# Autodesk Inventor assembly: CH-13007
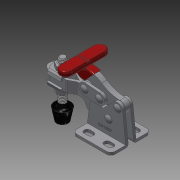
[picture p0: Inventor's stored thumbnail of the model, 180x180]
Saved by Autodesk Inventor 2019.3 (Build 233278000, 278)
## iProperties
Company: Î¢ÈíÖÐ¹ú
Created: 2012-09
Part Number: CH-13007
Material: Ogólny
Description: STEP AP203
Document SubType Name: Assembly
Designer: CADENGINEERING4
Stock Number: DOCISK PIONOWY
Sending System: SolidWorks 2010
Preprocessor: SwSTEP 2.0
Title: CH-13007.STEP
Author: Î¢ÈíÓÃ»§
Revision Number: ÈÎºÎ
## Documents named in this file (9)
- D:\Vault_2016\Projekty\Clamptek\STRONA\Vertical toggle clamp\CH-13007\CH-13007_ZAMNIETY.iam
- D:\Vault_2016\Projekty\Clamptek\STRONA\Vertical toggle clamp\CH-13007\CH-FC-56212 Nut.ipt
- D:\Vault_2016\Projekty\Clamptek\STRONA\Vertical toggle clamp\CH-13007\CH-13007-04 CONNECTING-PLATE.ipt
- D:\Vault_2016\Projekty\Clamptek\STRONA\Vertical toggle clamp\CH-13007\CH-13007-01 FLANGED BASE.ipt
- D:\Vault_2016\Projekty\Clamptek\STRONA\Vertical toggle clamp\CH-13007\CH-13007-05 .ipt
- D:\Vault_2016\Projekty\Clamptek\STRONA\Vertical toggle clamp\CH-13007\CH-FW-516.ipt
- D:\Vault_2016\Projekty\Clamptek\STRONA\Vertical toggle clamp\CH-13007\CH-FC-56212 SPINDLE SUPPLIED.ipt
- D:\Vault_2016\Projekty\Clamptek\STRONA\Vertical toggle clamp\CH-13007\CH-13007-02 U-BAR.ipt
- D:\Vault_2016\Projekty\Clamptek\STRONA\Vertical toggle clamp\CH-13007\CH-13007-03 T-HANDLE.ipt
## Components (14 placed, 14 different names)
1. CH-FC-56212 Nut_1 — Zestawiające:24, Zestawiające:25
2. CH-13007-04 CONNECTING-PLATE_2 — Zestawiające:5, Zestawiające:6, Zestawiające:10
3. CH-13007-01 FLANGED BASE_3 — Zestawiające:1, Zestawiające:2, Zestawiające:7, Zestawiające:8, Zestawiające:13, Zestawiające:14, Zestawiające:15, Zestawiające:16, Zestawiające:19
4. CH-13007-05 _4 — Zestawiające:11, Zestawiające:18
5. CH-FW-516_5 — Zestawiające:20, Zestawiające:22, Zestawiające:23, Kątowe:1, Zestawiające:24, Zestawiające:25
6. CH-FW-516_6 — Zestawiające:21, Zestawiające:22, Kątowe:2, Zestawiające:26, Zestawiające:27, Równoległe:1
7. CH-13007-05 _7 — Zestawiające:12, Zestawiające:17
8. CH-13007-05 _8 — Zestawiające:14, Zestawiające:15
9. CH-13007-04 CONNECTING-PLATE_9 — Zestawiające:3, Zestawiające:4, Zestawiające:9, Zestawiające:11, Zestawiające:12, Zestawiające:17, Zestawiające:18, Zestawiające:19
10. CH-FC-56212 SPINDLE SUPPLIED_10 — Zestawiające:28, Równoległe:1, Zestawiające:29
11. CH-13007-02 U-BAR_11 — Zestawiające:2, Zestawiające:4, Zestawiające:5, Zestawiające:8, Zestawiające:20, Zestawiające:21, Zestawiające:23, Kątowe:1, Kątowe:2, Zestawiające:29
12. CH-13007-05 _12 — Zestawiające:13, Zestawiające:16
13. CH-13007-03 T-HANDLE_13 — Zestawiające:1, Zestawiające:3, Zestawiające:6, Zestawiające:7, Zestawiające:9, Zestawiające:10
14. CH-FC-56212 Nut_14 — Zestawiające:26, Zestawiające:27, Zestawiające:28
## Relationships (32: Mate 29, Angle 2, Flush 1)
- Zestawiające:1 [Mate]: CH-13007-01 FLANGED BASE_3 ↔ CH-13007-03 T-HANDLE_13
- Zestawiające:2 [Mate]: CH-13007-01 FLANGED BASE_3 ↔ CH-13007-02 U-BAR_11
- Zestawiające:3 [Mate]: CH-13007-04 CONNECTING-PLATE_9 ↔ CH-13007-03 T-HANDLE_13
- Zestawiające:4 [Mate]: CH-13007-04 CONNECTING-PLATE_9 ↔ CH-13007-02 U-BAR_11
- Zestawiające:5 [Mate]: CH-13007-04 CONNECTING-PLATE_2 ↔ CH-13007-02 U-BAR_11
- Zestawiające:6 [Mate]: CH-13007-04 CONNECTING-PLATE_2 ↔ CH-13007-03 T-HANDLE_13
- Zestawiające:7 [Mate]: CH-13007-01 FLANGED BASE_3 ↔ CH-13007-03 T-HANDLE_13
- Zestawiające:8 [Mate]: CH-13007-01 FLANGED BASE_3 ↔ CH-13007-02 U-BAR_11
- Zestawiające:9 [Mate]: CH-13007-04 CONNECTING-PLATE_9 ↔ CH-13007-03 T-HANDLE_13
- Zestawiające:10 [Mate]: CH-13007-04 CONNECTING-PLATE_2 ↔ CH-13007-03 T-HANDLE_13
- Zestawiające:11 [Mate]: CH-13007-05 _4 ↔ CH-13007-04 CONNECTING-PLATE_9
- Zestawiające:12 [Mate]: CH-13007-05 _7 ↔ CH-13007-04 CONNECTING-PLATE_9
- Zestawiające:13 [Mate]: CH-13007-01 FLANGED BASE_3 ↔ CH-13007-05 _12
- Zestawiające:14 [Mate]: CH-13007-01 FLANGED BASE_3 ↔ CH-13007-05 _8
- Zestawiające:15 [Mate]: CH-13007-01 FLANGED BASE_3 ↔ CH-13007-05 _8
- Zestawiające:16 [Mate]: CH-13007-01 FLANGED BASE_3 ↔ CH-13007-05 _12
- Zestawiające:17 [Mate]: CH-13007-05 _7 ↔ CH-13007-04 CONNECTING-PLATE_9
- Zestawiające:18 [Mate]: CH-13007-05 _4 ↔ CH-13007-04 CONNECTING-PLATE_9
- Zestawiające:19 [Mate]: CH-13007-01 FLANGED BASE_3 ↔ CH-13007-04 CONNECTING-PLATE_9
- Zestawiające:20 [Mate]: CH-FW-516_5 ↔ CH-13007-02 U-BAR_11
- Zestawiające:21 [Mate]: CH-FW-516_6 ↔ CH-13007-02 U-BAR_11
- Zestawiające:22 [Mate]: CH-FW-516_5 ↔ CH-FW-516_6
- Zestawiające:23 [Mate]: CH-FW-516_5 ↔ CH-13007-02 U-BAR_11
- Kątowe:1 [Angle]: CH-FW-516_5 ↔ CH-13007-02 U-BAR_11
- Kątowe:2 [Angle]: CH-FW-516_6 ↔ CH-13007-02 U-BAR_11
- Zestawiające:24 [Mate]: CH-FC-56212 Nut_1 ↔ CH-FW-516_5
- Zestawiające:25 [Mate]: CH-FC-56212 Nut_1 ↔ CH-FW-516_5
- Zestawiające:26 [Mate]: CH-FW-516_6 ↔ CH-FC-56212 Nut_14
- Zestawiające:27 [Mate]: CH-FW-516_6 ↔ CH-FC-56212 Nut_14
- Zestawiające:28 [Mate]: CH-FC-56212 SPINDLE SUPPLIED_10 ↔ CH-FC-56212 Nut_14
- Równoległe:1 [Flush]: CH-FW-516_6 ↔ CH-FC-56212 SPINDLE SUPPLIED_10
- Zestawiające:29 [Mate]: CH-FC-56212 SPINDLE SUPPLIED_10 ↔ CH-13007-02 U-BAR_11
